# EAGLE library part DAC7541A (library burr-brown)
Low Cost 12-Bit CMOS DAC Four-Quadrant Multiplying
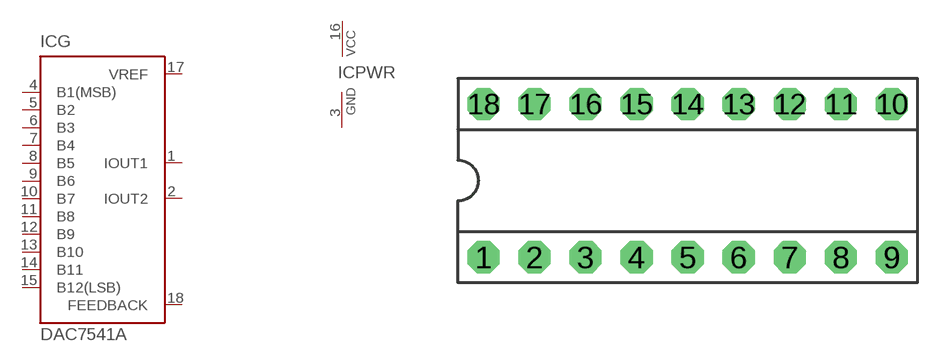
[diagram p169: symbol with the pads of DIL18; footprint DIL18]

Designator prefix IC; gates PWR=PWRN G=DAC7541A

## DAC7541AP (MF: TEXAS INSTRUMENTS; MPN: DAC7541AJP; OC_FARNELL: 1212269; OC_NEWARK: 96K4483)  [DIL18]
1  G:IOUT1  out
2  G:IOUT2  out
3  PWR:GND  pwr
4  G:B1(MSB)  in
5  G:B2  in
6  G:B3  in
7  G:B4  in
8  G:B5  in
9  G:B6  in
10  G:B7  in
11  G:B8  in
12  G:B9  in
13  G:B10  in
14  G:B11  in
15  G:B12(LSB)  in
16  PWR:VCC  pwr
17  G:VREF  pwr
18  G:FEEDBACK  pas

## Footprint DIL18 (pad centres in mm)
Dual In Line
drill 0.813 pad 1.6 octagon: 1 -10.16,-3.81; 2 -7.62,-3.81; 3 -5.08,-3.81; 4 -2.54,-3.81; 5 0,-3.81; 6 2.54,-3.81; 7 5.08,-3.81; 8 7.62,-3.81; 9 10.16,-3.81; 10 10.16,3.81; 11 7.62,3.81; 12 5.08,3.81; 13 2.54,3.81; 14 0,3.81; 15 -2.54,3.81; 16 -5.08,3.81; 17 -7.62,3.81; 18 -10.16,3.81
